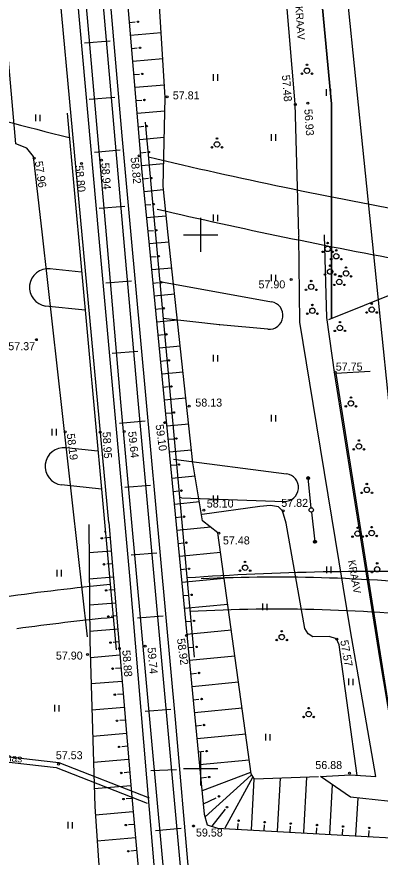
# Model space of a CAD drawing. Extents: x 9156 to 9809, y 2728 to 4000.
# Drawn here: x 9282.8 to 9316.8, y 3691.7 to 3770.4 of the extents above; entities that cross this region are included whole.
import ezdxf

# ---------------------------------------------------------------- set-up
doc = ezdxf.new("R2010")
doc.units = 0
for name, color, linetype in [('Level 1', 7, 'Continuous'), ('Level 17', 7, 'Continuous'), ('Level 18', 7, 'Continuous'), ('Level 54', 7, 'Continuous'), ('Level 56', 7, 'Continuous'), ('Level 58', 7, 'Continuous')]:
    doc.layers.add(name, color=color, linetype=linetype)

# ---------------------------------------------------------------- blocks, each defined once
blk = doc.blocks.new('KKOL')
at = {"layer": 'Level 58'}
for p, q in [((0, 1.59349), (0, -1.5935)), ((-1.5935, 0), (1.59349, 0))]:
    blk.add_line(p, q, dxfattribs=at)

msp = doc.modelspace()

# ---------------------------------------------------------------- linework, layer by layer
at = {"layer": 'Level 1'}
msp.add_line((9317.65, 3734.12), (9308.72, 3821.62), dxfattribs=at)
msp.add_line((9317.65, 3734.12), (9308.72, 3821.62), dxfattribs=at)
at = {"layer": 'Level 17'}
for centre, radius, start, end in [((9408.833, 4238.272), 494.25, 254.35277, 255.81316), ((9408.833, 4238.272), 494.25, 256.69765, 259.71972), ((9307.025, 3564.922), 153, 83.61424, 92.61532), ((9307.025, 3564.922), 150, 83.61424, 93.06688), ((9316.067, 3469.7), 245.65, 95.66807, 97.78514)]:
    msp.add_arc(centre, radius, start, end, dxfattribs=at)
at = {"layer": 'Level 18'}
for p, q in [((9287.492, 3761.374), (9292.082, 3711.12)), ((9294.814, 3760.537), (9299.392, 3710.413)), ((9288.852, 3746.481), (9285.874, 3746.801)), ((9296.177, 3745.619), (9306.637, 3743.721)), ((9289.177, 3742.926), (9285.488, 3743.322)), ((9301.769, 3741.573), (9296.494, 3742.14)), ((9306.283, 3741.148), (9301.785, 3741.571)), ((9290.383, 3729.721), (9287.379, 3730.044)), ((9297.469, 3728.96), (9308.023, 3727.603)), ((9290.708, 3726.166), (9286.968, 3726.568)), ((9298.206, 3725.361), (9298.025, 3725.38)), ((9298.206, 3725.361), (9307.81, 3725.015))]:
    msp.add_line(p, q, dxfattribs=at)
for centre, radius, start, end in [((9408.833, 4238.272), 498.82, 256.91824, 259.71972), ((9285.723, 3745.057), 1.75, 84.00648, 262.61085), ((9306.405, 3742.442), 1.3, 264.61977, 79.71972), ((9301.898, 3742.766), 1.2, 263.86829, 264.61977), ((9287.194, 3728.304), 1.75, 84.00648, 262.61085), ((9307.857, 3726.314), 1.3, 267.93485, 82.67276), ((9313.703, 3223.268), 499.4, 92.59709, 92.61077), ((9316.067, 3469.7), 248.75, 88.12497, 94.00034), ((9316.067, 3469.7), 248.75, 95.66247, 97.95082)]:
    msp.add_arc(centre, radius, start, end, dxfattribs=at)
at = {"layer": 'Level 54'}
for p, q in [((9285.974, 3835.845), (9292.631, 3759.251)), ((9288.908, 3750), (9285.684, 3784.749)), ((9290.478, 3750), (9287.344, 3784.693)), ((9310.269, 3783.12), (9312.251, 3762.246)), ((9312.251, 3762.246), (9310.269, 3783.12)), ((9293.341, 3769.889), (9293.865, 3769.933)), ((9296.308, 3768.91), (9293.444, 3768.668)), ((9289.129, 3767.961), (9291.53, 3768.158)), ((9293.547, 3767.447), (9294.071, 3767.491)), ((9296.462, 3766.463), (9293.65, 3766.225)), ((9293.754, 3765.004), (9294.277, 3765.048)), ((9301.183, 3765.035), (9301.183, 3764.415)), ((9301.589, 3765.024), (9301.589, 3764.415)), ((9296.615, 3764.016), (9293.857, 3763.783)), ((9311.743, 3763.634), (9311.743, 3763.013)), ((9312.149, 3763.622), (9312.149, 3763.013)), ((9289.57, 3762.703), (9291.971, 3762.9)), ((9293.96, 3762.562), (9294.484, 3762.606)), ((9312.251, 3762.246), (9312.251, 3750)), ((9312.251, 3750), (9312.251, 3762.246)), ((9296.656, 3761.56), (9294.063, 3761.34)), ((9284.525, 3761.256), (9284.525, 3760.636)), ((9284.931, 3761.245), (9284.931, 3760.636)), ((9294.167, 3760.119), (9294.69, 3760.164)), ((9292.631, 3759.251), (9293.476, 3750)), ((9296.593, 3759.094), (9294.27, 3758.898)), ((9306.589, 3759.415), (9306.589, 3758.795)), ((9306.995, 3759.404), (9306.995, 3758.795)), ((9290.06, 3757.74), (9292.461, 3757.937)), ((9294.373, 3757.677), (9294.897, 3757.721)), ((9296.53, 3756.629), (9294.476, 3756.456)), ((9294.587, 3755.235), (9295.11, 3755.286)), ((9296.517, 3754.191), (9294.705, 3754.015)), ((9294.823, 3752.795), (9295.347, 3752.846)), ((9290.501, 3752.482), (9292.902, 3752.679)), ((9296.78, 3751.753), (9294.941, 3751.575)), ((9300, 3751.593), (9300, 3750)), ((9300, 3751.593), (9300, 3750)), ((9300, 3751.25), (9300, 3748.75)), ((9301.183, 3751.884), (9301.183, 3751.264)), ((9301.589, 3751.873), (9301.589, 3751.264)), ((9295.059, 3750.356), (9295.583, 3750.406)), ((9291.411, 3723.027), (9288.908, 3750)), ((9293.365, 3718.046), (9290.478, 3750)), ((9293.476, 3750), (9297.624, 3704.585)), ((9298.407, 3750), (9301.593, 3750)), ((9298.407, 3750), (9301.593, 3750)), ((9298.407, 3750), (9301.593, 3750)), ((9298.407, 3750), (9301.593, 3750)), ((9298.75, 3750), (9301.25, 3750)), ((9300, 3750), (9300, 3748.407)), ((9300, 3750), (9300, 3748.407)), ((9309.286, 3741.803), (9309.174, 3749.868)), ((9311.552, 3749.937), (9311.778, 3742.234)), ((9331.65, 3750), (9311.976, 3742.025)), ((9312.251, 3750), (9312.25, 3742.216)), ((9312.25, 3742.216), (9312.251, 3750)), ((9297.043, 3749.316), (9295.177, 3749.136)), ((9295.296, 3747.916), (9295.819, 3747.967)), ((9297.307, 3746.879), (9295.414, 3746.696)), ((9291.135, 3745.482), (9293.536, 3745.679)), ((9306.589, 3746.264), (9306.589, 3745.644)), ((9306.995, 3746.253), (9306.995, 3745.644)), ((9295.532, 3745.476), (9296.055, 3745.527)), ((9297.57, 3744.442), (9295.65, 3744.256)), ((9295.768, 3743.036), (9296.291, 3743.087)), ((9297.834, 3742.005), (9295.886, 3741.817)), ((9310.517, 3734.181), (9309.286, 3741.803)), ((9311.778, 3742.234), (9312.523, 3736.92)), ((9296.004, 3740.597), (9296.527, 3740.647)), ((9298.097, 3739.568), (9296.122, 3739.377)), ((9291.723, 3738.898), (9294.124, 3739.094)), ((9301.183, 3738.733), (9301.183, 3738.113)), ((9301.589, 3738.722), (9301.589, 3738.113)), ((9296.24, 3738.157), (9296.764, 3738.208)), ((9298.361, 3737.131), (9296.358, 3736.937)), ((9315.853, 3737.184), (9312.645, 3737.011)), ((9312.645, 3737.011), (9318.631, 3699.076)), ((9312.523, 3736.92), (9316.73, 3710.352)), ((9296.476, 3735.717), (9297, 3735.768)), ((9298.624, 3734.694), (9296.594, 3734.497)), ((9314.036, 3712.898), (9310.517, 3734.181)), ((9296.713, 3733.277), (9297.236, 3733.328)), ((9306.589, 3733.113), (9306.589, 3732.493)), ((9306.995, 3733.102), (9306.995, 3732.493)), ((9292.409, 3732.362), (9294.81, 3732.559)), ((9286.059, 3731.826), (9286.059, 3731.206)), ((9286.465, 3731.815), (9286.465, 3731.206)), ((9298.887, 3732.257), (9296.831, 3732.058)), ((9296.949, 3730.838), (9297.472, 3730.888)), ((9299.151, 3729.82), (9297.067, 3729.618)), ((9297.185, 3728.398), (9297.708, 3728.449)), ((9299.485, 3727.389), (9297.303, 3727.178)), ((9310.336, 3724.42), (9310.065, 3727.207)), ((9292.898, 3726.352), (9295.299, 3726.549)), ((9297.421, 3725.958), (9297.944, 3726.009)), ((9301.183, 3725.582), (9301.183, 3724.962)), ((9301.589, 3725.57), (9301.589, 3724.962)), ((9299.888, 3724.966), (9297.539, 3724.738)), ((9310.379, 3724.022), (9310.702, 3721.241)), ((9297.657, 3723.518), (9298.181, 3723.569)), ((9300.944, 3722.605), (9297.775, 3722.299)), ((9291.527, 3721.623), (9291.003, 3721.58)), ((9297.893, 3721.079), (9298.417, 3721.129)), ((9289.549, 3720.229), (9291.629, 3720.402)), ((9293.486, 3720.014), (9295.887, 3720.21)), ((9301.867, 3720.232), (9298.011, 3719.859)), ((9291.73, 3719.181), (9291.206, 3719.137)), ((9311.786, 3718.918), (9311.786, 3718.298)), ((9312.191, 3718.906), (9312.191, 3718.298)), ((9286.535, 3718.614), (9286.535, 3717.994)), ((9286.94, 3718.603), (9286.94, 3717.994)), ((9298.13, 3718.639), (9298.653, 3718.69)), ((9289.574, 3717.772), (9291.831, 3717.959)), ((9296.984, 3675.228), (9293.365, 3718.046)), ((9302.203, 3717.802), (9298.248, 3717.419)), ((9291.933, 3716.738), (9291.409, 3716.694)), ((9298.366, 3716.199), (9298.889, 3716.25)), ((9289.6, 3715.315), (9292.034, 3715.517)), ((9302.539, 3715.372), (9298.484, 3714.979)), ((9305.803, 3715.441), (9305.803, 3714.821)), ((9306.209, 3715.429), (9306.209, 3714.821)), ((9292.135, 3714.295), (9291.611, 3714.252)), ((9294.074, 3714.117), (9296.475, 3714.314)), ((9298.602, 3713.76), (9299.125, 3713.81)), ((9289.609, 3712.856), (9292.237, 3713.074)), ((9302.874, 3712.942), (9298.72, 3712.54)), ((9316.406, 3699.235), (9314.036, 3712.898)), ((9292.338, 3711.852), (9291.814, 3711.809)), ((9298.838, 3711.32), (9299.361, 3711.37)), ((9314.637, 3699.355), (9312.976, 3711.592)), ((9289.681, 3710.402), (9292.439, 3710.631)), ((9303.21, 3710.512), (9298.956, 3710.1)), ((9316.73, 3710.352), (9318.631, 3699.076)), ((9292.541, 3709.41), (9292.017, 3709.366)), ((9299.074, 3708.88), (9299.598, 3708.931)), ((9289.754, 3707.949), (9292.642, 3708.188)), ((9303.545, 3708.082), (9299.192, 3707.66)), ((9313.825, 3708.418), (9313.825, 3707.798)), ((9314.231, 3708.407), (9314.231, 3707.798)), ((9292.743, 3706.967), (9292.219, 3706.923)), ((9299.31, 3706.44), (9299.834, 3706.491)), ((9286.331, 3705.954), (9286.331, 3705.334)), ((9286.736, 3705.943), (9286.736, 3705.334)), ((9289.826, 3705.495), (9292.845, 3705.746)), ((9294.809, 3705.37), (9297.21, 3705.567)), ((9303.881, 3705.651), (9299.428, 3705.22)), ((9292.946, 3704.524), (9292.422, 3704.481)), ((9297.624, 3704.585), (9307.22, 3593.093)), ((9299.547, 3704.001), (9300.07, 3704.051)), ((9289.899, 3703.042), (9293.047, 3703.303)), ((9304.217, 3703.221), (9299.665, 3702.781)), ((9306.075, 3703.237), (9306.075, 3702.617)), ((9306.481, 3703.225), (9306.481, 3702.617)), ((9293.149, 3702.081), (9292.625, 3702.038)), ((9299.783, 3701.561), (9300.306, 3701.612)), ((9278.715, 3700.978), (9286.461, 3700.104)), ((9278.845, 3701.462), (9286.739, 3700.572)), ((9289.971, 3700.588), (9293.25, 3700.86)), ((9304.552, 3700.791), (9299.901, 3700.341)), ((9300, 3701.25), (9300, 3698.75)), ((9286.461, 3700.104), (9294.992, 3696.74)), ((9286.739, 3700.572), (9295.189, 3697.239)), ((9298.75, 3700), (9301.25, 3700)), ((9293.351, 3699.639), (9292.827, 3699.595)), ((9295.343, 3699.802), (9297.749, 3699.917)), ((9304.666, 3699.618), (9300.137, 3697.901)), ((9304.719, 3699.379), (9300.416, 3695.469)), ((9311.214, 3699.235), (9314.021, 3699.395)), ((9314.021, 3697.322), (9311.214, 3699.235)), ((9314.021, 3699.395), (9316.406, 3699.235)), ((9290.044, 3698.135), (9293.452, 3698.417)), ((9300.019, 3699.121), (9300.542, 3699.172)), ((9304.852, 3699.166), (9302.268, 3694.395)), ((9304.978, 3699.008), (9304.716, 3694.26)), ((9307.438, 3699.096), (9307.163, 3694.124)), ((9309.898, 3699.183), (9309.611, 3693.989)), ((9312.314, 3698.486), (9312.058, 3693.854)), ((9293.555, 3697.196), (9293.031, 3697.149)), ((9300.255, 3696.681), (9301.461, 3697.254)), ((9335.451, 3694.95), (9314.021, 3697.322)), ((9314.701, 3697.247), (9314.505, 3693.719)), ((9301.071, 3694.6), (9302.309, 3696.191)), ((9290.147, 3695.658), (9293.665, 3695.975)), ((9287.554, 3694.994), (9287.554, 3694.374)), ((9287.96, 3694.983), (9287.96, 3694.374)), ((9293.775, 3694.755), (9293.252, 3694.708)), ((9303.492, 3694.327), (9303.521, 3694.852)), ((9305.94, 3694.192), (9305.969, 3694.717)), ((9308.387, 3694.057), (9308.416, 3694.582)), ((9295.787, 3694.198), (9298.186, 3694.416)), ((9310.834, 3693.921), (9310.863, 3694.446)), ((9313.282, 3693.786), (9313.311, 3694.311)), ((9315.729, 3693.651), (9315.758, 3694.176)), ((9290.313, 3693.212), (9293.886, 3693.534)), ((9293.996, 3692.314), (9293.472, 3692.266))]:
    msp.add_line(p, q, dxfattribs=at)
for points in [[(9269.25, 3999.973), (9271.259, 3976.19), (9273.902, 3944.866), (9276.45, 3917.737), (9281.296, 3864.068), (9286.975, 3797.782), (9291.142, 3750)], [(9292.133, 3966.797), (9292.975, 3956.086), (9305.56, 3800.91), (9308.813, 3762.254), (9309.17, 3750)], [(9275.527, 3944.686), (9278.045, 3917.884), (9282.891, 3864.208), (9288.57, 3797.92), (9292.749, 3750)], [(9296.707, 3908.817), (9282.928, 3908.232), (9282.231, 3907.963), (9281.85, 3907.526), (9281.903, 3906.879), (9285.716, 3859.807), (9294.504, 3755.854), (9295.071, 3750)], [(9296.97, 3750), (9296.477, 3754.558), (9296.689, 3762.847), (9295.42, 3783.044), (9294.943, 3788.676), (9292.72, 3813.984), (9290.868, 3845.928), (9290.656, 3847.576), (9291.239, 3849.648), (9288.595, 3875.599), (9286.16, 3902.861), (9286.425, 3903.605), (9287.961, 3904.508), (9295.43, 3907.164), (9296.278, 3907.323), (9296.913, 3907.642)], [(9285.182, 3750), (9284.361, 3757.323), (9283.725, 3758.109), (9282.696, 3758.502), (9280.491, 3783.544), (9280.834, 3784.133), (9281.618, 3784.477), (9282.157, 3784.87), (9282.255, 3785.264), (9282.155, 3787.891)], [(9289.401, 3712.325), (9285.182, 3750)], [(9291.142, 3750), (9292.509, 3734.326), (9298.237, 3671.484), (9304.697, 3595.661), (9311.403, 3518.763), (9313.026, 3500)], [(9292.749, 3750), (9294.103, 3734.468), (9299.832, 3671.625), (9306.292, 3595.799), (9312.998, 3518.901), (9314.633, 3500)], [(9295.071, 3750), (9300.327, 3695.705), (9300.595, 3694.735), (9301.563, 3694.411), (9315.023, 3693.667), (9338.834, 3692.345)], [(9311.037, 3699.223), (9305.05, 3699.011), (9304.732, 3699.489), (9301.612, 3722.085), (9300.181, 3723.201), (9299.281, 3728.62), (9296.97, 3750)], [(9309.17, 3750), (9309.174, 3749.868)], [(9311.551, 3750), (9311.552, 3749.937)], [(9307.992, 3722.968), (9307.65, 3724.139), (9307.277, 3724.512), (9306.533, 3724.627), (9305.53, 3724.541), (9300.145, 3723.794)], [(9289.521, 3722.865), (9289.636, 3711.949), (9290.094, 3696.436), (9293.302, 3649.242), (9295.59, 3619.198), (9296.851, 3602.192), (9300.163, 3556.342), (9301.424, 3542.094), (9302.684, 3538.991), (9304.632, 3528.075), (9306.915, 3513.758), (9308.634, 3504.221), (9309.025, 3500)], [(9291.411, 3723.027), (9293.543, 3697.334), (9296.97, 3659.378), (9299.033, 3634.903), (9302.12, 3597.158), (9303.724, 3578.543), (9308.876, 3518.425), (9310.547, 3500)], [(9312.976, 3711.592), (9312.718, 3712.138), (9312.031, 3712.368), (9310.484, 3712.339), (9310.054, 3712.626), (9309.739, 3713.115), (9307.992, 3722.968)]]:
    msp.add_lwpolyline(points, dxfattribs=at)
for centre, radius in [((9294.12, 3769.947), 0.0683), ((9294.326, 3767.505), 0.0683), ((9309.953, 3765.361), 0.25), ((9309.953, 3765.911), 0.0707), ((9294.533, 3765.062), 0.0683), ((9309.477, 3765.086), 0.0707), ((9310.429, 3765.086), 0.0707), ((9296.862, 3762.911), 0.0909), ((9294.739, 3762.62), 0.0683), ((9308.86, 3762.189), 0.0909), ((9310.043, 3762.326), 0.0909), ((9294.946, 3760.178), 0.0683), ((9301.529, 3759.015), 0.0707), ((9301.052, 3758.19), 0.0707), ((9301.529, 3758.465), 0.25), ((9302.005, 3758.19), 0.0707), ((9294.254, 3757.396), 0.0909), ((9295.152, 3757.735), 0.0683), ((9284.423, 3757.167), 0.0909), ((9288.838, 3756.665), 0.0909), ((9290.708, 3756.988), 0.0909), ((9295.365, 3755.303), 0.0683), ((9295.602, 3752.863), 0.0683), ((9295.838, 3750.423), 0.0683), ((9311.888, 3748.671), 0.25), ((9311.888, 3749.221), 0.0707), ((9296.074, 3747.984), 0.0683), ((9311.411, 3748.396), 0.0707), ((9312.364, 3748.396), 0.0707), ((9312.69, 3747.982), 0.25), ((9312.69, 3748.532), 0.0707), ((9312.213, 3747.707), 0.0707), ((9313.166, 3747.707), 0.0707), ((9312.117, 3746.546), 0.25), ((9312.117, 3747.096), 0.0707), ((9313.606, 3746.373), 0.25), ((9313.606, 3746.923), 0.0707), ((9308.476, 3745.811), 0.0909), ((9310.342, 3745.665), 0.0707), ((9311.64, 3746.271), 0.0707), ((9312.593, 3746.271), 0.0707), ((9312.977, 3745.574), 0.25), ((9312.977, 3746.124), 0.0707), ((9313.13, 3746.098), 0.0707), ((9314.082, 3746.098), 0.0707), ((9296.31, 3745.544), 0.0683), ((9309.866, 3744.84), 0.0707), ((9310.342, 3745.115), 0.25), ((9310.819, 3744.84), 0.0707), ((9312.501, 3745.299), 0.0707), ((9313.454, 3745.299), 0.0707), ((9310.457, 3743.424), 0.0707), ((9316.014, 3743.539), 0.0707), ((9296.546, 3743.104), 0.0683), ((9309.98, 3742.599), 0.0707), ((9310.457, 3742.874), 0.25), ((9310.933, 3742.599), 0.0707), ((9315.537, 3742.714), 0.0707), ((9316.014, 3742.989), 0.25), ((9316.49, 3742.714), 0.0707), ((9313.035, 3741.815), 0.0707), ((9312.558, 3740.99), 0.0707), ((9313.035, 3741.265), 0.25), ((9313.511, 3740.99), 0.0707), ((9284.62, 3740.168), 0.0909), ((9296.782, 3740.664), 0.0683), ((9297.019, 3738.225), 0.0683), ((9312.594, 3737.116), 0.0909), ((9297.255, 3735.785), 0.0683), ((9314.066, 3734.748), 0.0707), ((9298.93, 3733.929), 0.0909), ((9313.59, 3733.923), 0.0707), ((9314.066, 3734.198), 0.25), ((9314.542, 3733.923), 0.0707), ((9297.491, 3733.345), 0.0683), ((9296.652, 3732.395), 0.0909), ((9287.305, 3731.543), 0.0909), ((9290.602, 3731.509), 0.0909), ((9292.845, 3731.577), 0.0909), ((9297.727, 3730.906), 0.0683), ((9314.811, 3730.726), 0.0707), ((9314.334, 3729.901), 0.0707), ((9314.811, 3730.176), 0.25), ((9315.287, 3729.901), 0.0707), ((9297.963, 3728.466), 0.0683), ((9310.065, 3727.207), 0.136), ((9310.065, 3727.207), 0.121), ((9310.065, 3727.207), 0.107), ((9310.065, 3727.207), 0.0902), ((9310.065, 3727.207), 0.0749), ((9310.065, 3727.207), 0.0616), ((9310.065, 3727.207), 0.0468), ((9310.065, 3727.207), 0.0343), ((9310.065, 3727.207), 0.0209), ((9310.065, 3727.207), 0.0112), ((9298.199, 3726.026), 0.0683), ((9315.555, 3726.097), 0.25), ((9315.555, 3726.647), 0.0707), ((9315.079, 3725.822), 0.0707), ((9316.032, 3725.822), 0.0707), ((9310.356, 3724.221), 0.2), ((9310.356, 3724.221), 0.2), ((9298.436, 3723.586), 0.0683), ((9300.306, 3724.198), 0.0909), ((9307.716, 3724.13), 0.0909), ((9301.7, 3722.05), 0.0909), ((9314.689, 3721.997), 0.25), ((9314.689, 3722.547), 0.0707), ((9316.007, 3722.054), 0.25), ((9316.007, 3722.604), 0.0707), ((9290.748, 3721.566), 0.0683), ((9310.702, 3721.241), 0.136), ((9310.702, 3721.241), 0.121), ((9310.702, 3721.241), 0.107), ((9310.702, 3721.241), 0.0902), ((9310.702, 3721.241), 0.0749), ((9310.702, 3721.241), 0.0616), ((9310.702, 3721.241), 0.0468), ((9310.702, 3721.241), 0.0343), ((9310.702, 3721.241), 0.0209), ((9310.702, 3721.241), 0.0112), ((9314.213, 3721.722), 0.0707), ((9315.166, 3721.722), 0.0707), ((9315.531, 3721.779), 0.0707), ((9316.483, 3721.779), 0.0707), ((9298.672, 3721.147), 0.0683), ((9290.951, 3719.124), 0.0683), ((9304.155, 3718.801), 0.25), ((9304.155, 3719.351), 0.0707), ((9316.523, 3718.664), 0.25), ((9316.523, 3719.214), 0.0707), ((9298.908, 3718.707), 0.0683), ((9303.679, 3718.526), 0.0707), ((9304.631, 3718.526), 0.0707), ((9316.046, 3718.389), 0.0707), ((9291.153, 3716.681), 0.0683), ((9299.144, 3716.267), 0.0683), ((9291.356, 3714.238), 0.0683), ((9299.38, 3713.827), 0.0683), ((9307.592, 3712.858), 0.0707), ((9291.559, 3711.795), 0.0683), ((9298.678, 3712.453), 0.0909), ((9307.116, 3712.033), 0.0707), ((9307.592, 3712.308), 0.25), ((9308.069, 3712.033), 0.0707), ((9312.75, 3712.109), 0.0909), ((9292.389, 3711.226), 0.0909), ((9294.803, 3711.465), 0.0909), ((9299.616, 3711.388), 0.0683), ((9289.394, 3710.672), 0.0909), ((9291.761, 3709.353), 0.0683), ((9299.853, 3708.948), 0.0683), ((9291.964, 3706.91), 0.0683), ((9300.089, 3706.508), 0.0683), ((9310.112, 3705.65), 0.0707), ((9309.635, 3704.825), 0.0707), ((9310.112, 3705.1), 0.25), ((9310.588, 3704.825), 0.0707), ((9292.167, 3704.467), 0.0683), ((9300.325, 3704.068), 0.0683), ((9292.369, 3702.024), 0.0683), ((9300.561, 3701.629), 0.0683), ((9286.702, 3700.398), 0.0909), ((9292.572, 3699.582), 0.0683), ((9300.797, 3699.189), 0.0683), ((9313.935, 3699.556), 0.0909), ((9292.776, 3697.133), 0.0683), ((9301.722, 3697.387), 0.0683), ((9302.465, 3696.375), 0.0683), ((9292.996, 3694.692), 0.0683), ((9299.319, 3694.613), 0.0909), ((9303.543, 3695.107), 0.0683), ((9305.99, 3694.972), 0.0683), ((9308.438, 3694.836), 0.0683), ((9310.885, 3694.701), 0.0683), ((9313.332, 3694.566), 0.0683), ((9315.78, 3694.43), 0.0683), ((9293.217, 3692.251), 0.0683)]:
    msp.add_circle(centre, radius, dxfattribs=at)
at = {"layer": 'Level 56'}
for p, q in [((9287.492, 3761.374), (9292.082, 3711.12)), ((9294.814, 3760.537), (9299.392, 3710.413)), ((9288.852, 3746.481), (9285.874, 3746.801)), ((9296.177, 3745.619), (9306.637, 3743.721)), ((9289.177, 3742.926), (9285.488, 3743.322)), ((9301.769, 3741.573), (9296.494, 3742.14)), ((9306.283, 3741.148), (9301.785, 3741.571)), ((9290.383, 3729.721), (9287.379, 3730.044)), ((9297.469, 3728.96), (9308.023, 3727.603)), ((9290.708, 3726.166), (9286.968, 3726.568)), ((9298.206, 3725.361), (9298.025, 3725.38)), ((9298.206, 3725.361), (9307.81, 3725.015))]:
    msp.add_line(p, q, dxfattribs=at)
for centre, radius, start, end in [((9408.833, 4238.272), 494.25, 254.35277, 255.81316), ((9408.833, 4238.272), 494.25, 256.69765, 259.71972), ((9408.833, 4238.272), 498.82, 256.91824, 259.71972), ((9285.723, 3745.057), 1.75, 84.00648, 262.61085), ((9306.405, 3742.442), 1.3, 264.61977, 79.71972), ((9301.898, 3742.766), 1.2, 263.86829, 264.61977), ((9287.194, 3728.304), 1.75, 84.00648, 262.61085), ((9307.857, 3726.314), 1.3, 267.93485, 82.67276), ((9313.703, 3223.268), 499.4, 92.59709, 92.61077), ((9316.067, 3469.7), 248.75, 88.12497, 94.00034), ((9307.025, 3564.922), 153, 83.61424, 92.61532), ((9316.067, 3469.7), 248.75, 95.66247, 97.95082), ((9307.025, 3564.922), 150, 83.61424, 93.06688), ((9316.067, 3469.7), 245.65, 95.66807, 97.78514)]:
    msp.add_arc(centre, radius, start, end, dxfattribs=at)

# ---------------------------------------------------------------- block references
at = {"layer": 'Level 54'}
msp.add_blockref('KKOL', (9300, 3700), dxfattribs=at)

# ---------------------------------------------------------------- texts
for s, height, rotation, p in [('KRAAV', 0.7, 274.09378, (9308.856, 3771.386)), ('57.48', 0.75, 274.62207, (9307.605, 3764.942)), ('56.93', 0.75, 273.93381, (9309.699, 3761.755)), ('57.96', 0.75, 278.38833, (9284.464, 3756.843)), ('58.94', 0.75, 274.01675, (9290.689, 3756.712)), ('58.82', 0.75, 276.02666, (9293.437, 3757.221)), ('58.80', 0.75, 275.75768, (9288.245, 3756.467)), ('58.95', 0.75, 273.49354, (9290.806, 3731.513)), ('59.64', 0.75, 276.50114, (9293.198, 3731.541)), ('59.10', 0.75, 277.90438, (9295.775, 3732.187)), ('58.19', 0.75, 277.20352, (9287.458, 3731.342)), ('KRAAV', 0.7, 280.09599, (9313.783, 3719.459)), ('58.92', 0.75, 277.88463, (9297.777, 3712.136)), ('57.57', 0.75, 280.1257, (9313.062, 3711.963)), ('58.88', 0.75, 274.74996, (9292.656, 3711.058)), ('59.74', 0.75, 275.39216, (9295.016, 3711.316)), ('pinnas', 0.7, 354.32003, (9280.529, 3700.828))]:
    msp.add_text(s, height=height, rotation=rotation, dxfattribs=at).set_placement(p)
for s, p in [('57.81', (9297.39, 3762.681)), ('57.90', (9305.411, 3744.974)), ('57.37', (9281.992, 3739.183)), ('57.75', (9312.648, 3737.269)), ('58.13', (9299.502, 3733.901)), ('58.10', (9300.571, 3724.444)), ('57.82', (9307.546, 3724.505)), ('57.48', (9302.084, 3720.988)), ('57.90', (9286.447, 3710.2)), ('57.53', (9286.441, 3700.867)), ('56.88', (9310.732, 3699.949)), ('59.58', (9299.557, 3693.625))]:
    msp.add_text(s, height=0.75, dxfattribs=at).set_placement(p)

doc.saveas('drawing.dxf')
